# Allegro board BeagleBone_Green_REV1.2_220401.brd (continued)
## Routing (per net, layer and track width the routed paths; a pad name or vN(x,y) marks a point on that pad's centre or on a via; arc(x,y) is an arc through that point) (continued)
EHRPWM2B: length 23.7
  TOP w0.121: v1(44.92,34.81) U5.T10
  LYR3 w0.133: v1(44.92,34.81) 44.38,35.35 44.38,35.73 43.38,36.73 43.38,40.68 41.55,42.52 37.87,42.52 35.81,44.58 34.78,44.58 33.89,45.46 33.89,49.13 P8.13
EMMC_RSTN: length 4.8
  TOP w0.203: U13.K5 28.7,43.26 v1(28.7,43.69)
  BOTTOM w0.121: R111.2 26.7,46.46 R162.2 ; R162.2 27.51,46.53 ; R162.2 27.51,44.88 v1(28.7,43.69)
EMMC_VCCI: length 2.1
  TOP w0.076: U13.C2 32.05,44.9 32.05,45.05 32.05,45.06 32.05,45.26 32.05,45.27 32.05,45.53
  TOP w0.121: v1(32.38,45.83) 32.37,45.83 32.36,45.82 32.35,45.82 32.05,45.53
  BOTTOM w0.121: C125.1 v1(32.38,45.83)
ENZ_KALDO_1P8V: length 3.4
  TOP w0.121: U5.B4 v1(50.52,22.81)
  BOTTOM w0.121: v1(50.52,22.81) 51.12,22.21 R54.2
ETH_RESETN: length 6.3
  TOP w0.121: U14.19 v1(25.83,34.61)
  BOTTOM w0.121: U1.4 27.2,37.74 26.8,37.34 R35.2 25.91,35.06 25.83,34.99 v1(25.83,34.61)
  BOTTOM w0.127: C27.1 R35.2
ETH_RST_GPIO1_8: length 36.7
  TOP w0.121: U5.E18 38.18,25.61 37.97,25.4 36.04,25.4 34.04,23.39 34.04,19.66 33.29,18.91 32.47,18.91 31.24,20.14 31.24,21.08 30.73,21.59 v1(30.73,24.02)
  LYR4 w0.133: v1(30.61,40.13) 30.61,37.85 30.73,37.72 30.73,25.78 31.24,25.27 31.24,24.53 v1(30.73,24.02)
  BOTTOM w0.121: U1.1 30.62,39.04 30.7,38.96 R34.2 31.14,39.6 v1(30.61,40.13)
ETH_TXD4: length 4.4
  TOP w0.121: U14.18 26.33,34.21 26.73,34.61 v1(29.21,34.61)
  BOTTOM w0.121: R145.1 v1(29.21,34.61)
GPIO0_7: length 45.8
  TOP w0.121: v1(36.07,18.03) 36.32,18.29 R50.1
  BOTTOM w0.121: P9.42 68.9,6.03 67.45,6.03 60.42,13.06 42.97,13.06 41.27,14.76 41.27,17.91 40.64,18.54 R51.1 39.75,19.18 39.37,19.56 37.85,19.56 37.21,20.19 36.7,20.19 36.47,19.96 36.47,19.45 36.07,19.05 v1(36.07,18.03)
GPIO0_7SRC: length 9.2
  TOP w0.121: R50.2 36.07,17.27 35.61,17.73 35.61,19.99 37.08,21.46 37.08,22.48 38.62,24.01 U5.C18
GPIO0_26: length 27.2
  TOP w0.121: v1(44.12,34.81) U5.T11
  LYR3 w0.133: P8.14 33.66,51.44 33.66,43.52 34.91,42.27 41.47,42.27 43.1,40.63 43.1,36.5 44.12,35.48 v1(44.12,34.81)
GPIO0_27: length 18.3
  TOP w0.121: U5.U12 44.12,35.61 44.12,36.17 43.56,36.73 43.56,44.7 43.95,45.09 43.95,48.28 43.01,49.22 40.95,49.22 P8.17
GPIO1_12: length 27.6
  TOP w0.121: v1(43.32,34.81) U5.T12
  LYR3 w0.133: P8.12 31.43,51.75 31.43,45.07 34.74,41.76 41.31,41.76 42.49,40.57 42.49,36.25 43.32,35.42 v1(43.32,34.81)
GPIO1_13: length 26
  TOP w0.121: v1(43.32,34.01) U5.R12
  LYR3 w0.121: 43.72,35.45 43.72,34.41 v1(43.32,34.01)
  LYR3 w0.133: 43.72,35.45 42.8,36.37 42.8,40.6 41.38,42.02 34.81,42.02 31.71,45.13 31.71,49.49 P8.11
GPIO1_14: length 22
  TOP w0.121: U5.V13 42.92,36.22 42.82,36.32 42.82,43.1 41.67,44.25 41.67,47.59 41.12,48.13 37.8,48.13 36.2,49.73 36.2,51.44 P8.16
GPIO1_15: length 19.4
  TOP w0.121: P8.15 37.47,49.07 38.03,48.51 41.15,48.51 41.92,47.75 41.92,44.36 43.07,43.21 43.07,36.43 43.32,36.17 43.32,35.61 U5.U13
GPIO1_16: length 55.9
  LYR4 w0.133: P9.15 36.32,3.05 32.26,3.05 31.24,4.06 31.24,6.86 31.75,7.37 31.75,18.95 31.24,19.46 31.24,21.79 33.53,24.08 33.53,37.21 35.56,39.24 37.72,39.24 37.97,39.5 37.97,42.09 38.82,42.94 v1(42.42,42.94)
  BOTTOM w0.133: v1(42.42,42.94) R160.2 R161.2
GPIO1_17: length 53.4
  TOP w0.121: v1(41.4,38.58) 41.45,38.58 42.12,37.92 U5.V14
  LYR4 w0.133: v1(35.31,6.48) 35.31,8.81 36.47,9.98 36.47,18.49 35.66,19.3 35.66,22.96 35.81,23.11 35.81,25.68 36.3,26.16 36.3,26.97 37.7,28.37 37.7,33.56 40.69,36.55 40.69,37.91 41.36,38.58 v1(41.4,38.58)
  BOTTOM w0.121: v1(35.31,6.48) 36.2,5.59 45.59,5.59 46.35,4.83 46.35,3.17 P9.23
GPIO1_28: length 38.6
  TOP w0.121: v1(37.01,37.34) 37.01,37.34 37.57,36.78 37.57,36.33 37.76,36.14 37.76,36.1 38.65,35.21 U5.U18
  LYR4 w0.133: v1(37.01,37.34) 36.96,37.34 36.53,36.91 36.53,36.63 36.31,36.41 35.14,36.41 34.29,35.56 34.29,22.1 34.27,22.08 34.27,22 34.04,21.77 34.04,17.78 32.66,16.41 32.66,5.87 32.38,5.59 P9.12
GPIO1_29: length 18.7
  TOP w0.121: P8.26 49.22,52.7 48.82,52.31 48.82,49.15 49.7,48.27 49.7,46.03 49.7,46.03 49.7,45.7 49.7,45.7 49.7,45.22 49.07,44.59 49.07,39.21 48.52,38.66 U5.V6
GPIO2_1: length 20.1
  TOP w0.121: P8.18 38.84,51.54 38.84,49.63 39.52,48.95 41.1,48.95 42.16,47.88 42.16,44.46 43.31,43.31 43.31,36.53 43.72,36.12 U5.V12
GPIO3_18: length 5.9
  TOP w0.121: U5.B12 43.32,22.81 43.32,22.23 42.6,21.52 42.09,21.52 40.77,20.19 v1(40.01,20.19)
  BOTTOM w0.121: v1(40.01,20.19) R51.2
GPIO3_19: length 28.2
  TOP w0.121: v1(42.52,23.61) U5.C13
  LYR4 w0.133: v1(42.52,23.61) 41.85,22.94 41.85,21.67 42.38,21.15 42.38,17.36 42.93,16.81 42.93,14 45.19,11.73 45.19,10.39 46.48,9.09 46.48,7.21 48.77,4.93 48.77,3.81 49.53,3.05 51.56,3.05 P9.27
GPIO3_20: length 5.9
  TOP w0.121: U5.D13 v1(42.52,25.21)
  BOTTOM w0.121: R20.2 42.55,20.95 42.12,21.38 42.12,24.81 v1(42.52,25.21)
GPIO3_21: length 59.2
  TOP w0.121: v1(38.75,41.34) 38.68,41.4 38.35,41.4 37.97,41.78 ; U5.A14 42.12,22.21 40.74,20.83 39.75,20.83 v1(39.12,20.19) 38.99,20.07 38.99,16.64 40.39,15.24 40.39,11.23 41.25,10.36 41.25,6.88 41.78,6.35 44.2,6.35 44.93,5.61 48.23,5.61 48.9,4.95 48.9,3.17 P9.25
  LYR3 w0.133: v1(35.05,23.55) 34.54,23.04 34.54,21.84 35.43,20.95 37.97,20.95 38.73,20.19 v1(39.12,20.19)
  LYR4 w0.133: v1(35.05,23.55) 35.05,34.16 35.31,34.42 37.34,34.42 38.73,35.81 38.73,36.32 38.48,36.58 38.48,41.07 v1(38.75,41.34)
GRN_C: length 2
  BOTTOM w0.381: P5.10 4.88,32.59 5.21,32.26 R132.2
GRNA: length 30.1
  TOP w0.121: v1(24.4,27.73) 24.33,27.8
  TOP w0.254: 24.33,27.8 U14.3
  BOTTOM w0.254: v1(24.4,27.73) 24.09,28.04 23.73,28.04 22.99,27.3 20.95,27.3 17.78,24.13 15.11,24.13 12.19,27.05 10.79,27.05 7.62,30.23 7.62,31.88 6.73,32.77 6.73,33.53 5.08,35.18 4.34,35.18 P5.9
HDMI_INT: length 12.2
  TOP w0.121: U5.U16 40.12,35.61 40.12,36.76 v1(39.86,37.02)
  BOTTOM w0.121: R170.1 R169.1 37.72,39.24 36.7,39.24 36.32,38.86 36.32,38.1 36.58,37.85 36.58,36.58 36.96,36.2 37.34,36.2 37.71,35.82 39.88,35.82 40.01,35.94 40.01,36.88 v1(39.86,37.02)
HDMICLK_DISN: length 5.4
  TOP w0.121: v1(39.5,39.5) 39.5,39.62 39.75,39.87 39.77,39.87 40.34,40.45 Y4.1 ; U5.V17 39.72,36.23 39.5,36.45 39.5,36.45 v1(39.49,36.46)
  LYR3 w0.133: v1(39.49,36.46) 39.46,36.5 39.46,39.46 v1(39.5,39.5)
I2C0_SCL: length 27.9
  TOP w0.121: R3.2 26.04,20.45 v1(26.92,19.56) ; U2.28 26.72,14.24 v1(26.92,14.03) ; v1(40.12,23.61) U5.C16
  LYR4 w0.133: v1(26.92,19.56) 27.56,18.92 27.56,14.67 v1(26.92,14.03)
  BOTTOM w0.121: v1(40.12,23.61) 39.72,23.21 39.72,21.69 39.14,21.1 37.67,21.1 36.17,22.61 31.98,22.61 31.72,22.86 U7.1 30.1,22.86 28.98,21.74 28.98,20.34 28.19,19.56 v1(26.92,19.56)
I2C0_SDA: length 33.2
  TOP w0.121: U2.27 26.48,13.84 v1(26.92,13.4) ; v1(36.07,19.68) 36.07,20.1 37.33,21.36 37.33,21.41 37.34,21.41 37.34,22.23 38.72,23.61 39.32,23.61 U5.C17 ; R4.2 v1(26.99,20.57)
  LYR3 w0.133: v1(36.07,19.68) 34.8,19.68 33.27,21.21 27.62,21.21 v1(26.99,20.57)
  LYR4 w0.133: v1(26.92,13.4) 27.81,14.29 27.81,19.75 v1(26.99,20.57)
  BOTTOM w0.121: v1(26.99,20.57) 26.42,20 26.42,19.3 26.67,19.05 28.32,19.05 29.34,20.07 30.48,20.07 30.82,20.41 U7.3
I2C1_SCL: length 25.2
  TOP w0.121: U5.A16 v1(40.12,22.01)
  TOP w0.133: v1(40.01,6.99) 40.01,6.73 41.15,5.59 41.15,3.05 P9.17
  LYR4 w0.133: v1(40.01,6.99) 43.31,10.29 43.48,10.29 44.25,11.06 44.25,11.67 41.87,14.05 41.87,14.85 41.23,15.49 41.23,20.75 40.12,21.86 v1(40.12,22.01)
I2C1_SDA: length 23.1
  TOP w0.121: U5.B16 v1(40.12,22.81)
  LYR4 w0.133: v1(40.12,22.81) 39.71,22.4 39.71,21.83 41,20.55 41,15.4 41.64,14.76 41.64,13.95 44.02,11.57 44.02,11.16 43.4,10.54 42.99,10.54 39.6,7.15 39.6,4.85 P9.18
I2C2_SCL: length 74.8
  TOP w0.121: v1(36.7,23.37) 37.47,23.37 38.51,24.41 39.32,24.41 U5.D17 ; J4.1 74.19,21.54 v1(73.66,21.02)
  LYR3 w0.133: v1(39.73,13.59) 44.42,13.59 47.6,10.41 53.21,10.41 55.65,12.85 68.61,12.85 73.66,17.91 v1(73.66,21.02)
  LYR4 w0.133: P9.19 41.4,3.05 39.42,3.05 38.63,3.84 38.63,12.49 v1(39.73,13.59) 37.47,15.85 37.47,20.35 37.1,20.71 37.1,22.97 v1(36.7,23.37)
  BOTTOM w0.121: v1(73.66,21.02) 73.15,21.52 R177.2
I2C2_SDA: length 72.9
  TOP w0.121: J4.2 v1(74.3,19.54) ; v1(36.7,24) 36.83,23.88 37.47,23.88 38.4,24.81 U5.D18
  LYR3 w0.133: v1(39.88,12.83) 40.13,13.08 44.53,13.08 47.43,10.18 53.41,10.18 55.8,12.57 68.82,12.57 74.02,17.78 74.02,19.27 v1(74.3,19.54)
  LYR4 w0.133: P9.20 41.53,3.43 39.37,3.43 38.86,3.94 38.86,11.81 v1(39.88,12.83) 40.15,13.1 40.15,13.74 39.79,14.1 39.66,14.1 37.74,16.01 37.74,20.52 37.34,20.93 37.34,23.37 v1(36.7,24)
  BOTTOM w0.121: v1(74.3,19.54) 73.92,19.54 73.91,19.53 R178.2
JTAG_EMU0: length 23.6
  TOP w0.121: v1(41.72,23.61) U5.C14 ; R23.2 36.06,11.87 34.29,13.64 v1(34.29,14.92)
  LYR3 w0.133: v1(34.29,14.92) 34.86,15.49 38.35,15.49 38.61,15.75 v1(42.42,15.75)
  LYR4 w0.133: v1(41.72,23.61) 41.72,23.24 41.59,23.11 41.59,21.55 41.96,21.18 41.96,21.11 41.97,21.1 41.97,16.19 v1(42.42,15.75)
  BOTTOM w0.121: P2.13 v1(34.29,14.92)
JTAG_EMU1: length 15.3
  TOP w0.121: R24.2 36.26,15.11 v1(36.07,14.92) ; v1(39.73,15.24) 39.65,15.24 38.59,16.3 38.59,20.3 39.5,21.21 40.77,21.21 41.72,22.16 41.72,22.81 U5.B14
  BOTTOM w0.121: v1(36.07,14.92) P2.14 39.18,14.92 39.5,15.24 v1(39.73,15.24)
JTAG_TCK: length 24.1
  TOP w0.121: U5.A12 43.72,22.26 43.4,21.94 43.4,21.94 42.73,21.27 42.35,21.27 40.39,19.3 40.39,15.88 40.89,15.37 40.89,12.19 v1(41.15,11.94)
  LYR3 w0.133: v1(34.29,12.38) 40.7,12.38 v1(41.15,11.94)
  BOTTOM w0.121: P2.9 v1(34.29,12.38) 34.29,13.46 34.1,13.65 P2.11
JTAG_TDI: length 24.1
  TOP w0.121: U5.B11 44.12,22.81 44.12,22.17 42.87,20.92 42.51,20.92 40.8,19.21 40.8,16.06 41.27,15.59 41.27,12.42 v1(41.8,11.9)
  BOTTOM w0.121: v1(41.8,11.9) 41.42,11.52 40.5,11.52 39.46,10.48 36.26,10.48 34.35,8.57 P2.3
JTAG_TDO: length 23.7
  TOP w0.121: U5.A11 44.52,22.04 44.2,21.72 44.2,21.08 43.56,20.45 42.54,20.45 42.54,20.44 41.15,19.05 41.15,16.32 41.66,15.81 41.66,12.85 42.32,12.19 42.32,11.71 v1(41.83,11.23)
  LYR3 w0.133: v1(34.29,11.11) 35.04,11.86 40.18,11.86 40.82,11.23 v1(41.83,11.23)
  BOTTOM w0.121: P2.7 v1(34.29,11.11)
JTAG_TMS: length 29
  TOP w0.121: U5.C11 v1(44.12,23.61) ; v1(44.2,8.89) 44.64,9.33 44.64,14.26 45.09,14.71 v1(45.09,15.95)
  LYR4 w0.133: v1(44.12,23.61) 44.12,21.87 44.39,21.6 44.39,16.27 44.7,15.95 v1(45.09,15.95)
  BOTTOM w0.121: v1(44.2,8.89) 43.69,9.4 41.66,9.4 40.2,7.94 35.5,7.94 34.86,7.3 P2.1
JTAG_TRSTN: length 25.6
  TOP w0.121: R25.1 36.83,7.49 36.64,7.3 v1(36.07,7.3) ; v1(42.55,8.89) 42.57,8.92 42.57,12.42 41.91,13.08 41.91,16 41.4,16.51 41.4,18.92 42.67,20.19 43.69,20.19 44.45,20.95 44.45,21.59 44.92,22.06 44.92,22.81 U5.B10
  BOTTOM w0.121: v1(42.55,8.89) 41.66,8.89 40.26,7.49 39.12,7.49 38.93,7.3 P2.2 v1(36.07,7.3)
LCD_DATA0: length 34.3
  TOP w0.121: U5.R1 52.63,33.61 53.92,34.9 57.25,34.9 v1(57.89,35.53) ; R95.1 v1(75.95,48.26)
  LYR3 w0.133: v1(75.95,48.26) 75.44,47.75 74.17,47.75 72.77,46.35 72.77,45.34 72.14,44.7 71.37,44.7 68.45,41.78 65.91,41.78 65.02,40.89 62.1,40.89 60.96,39.75 60.96,38.61 v1(57.89,35.53)
  BOTTOM w0.121: P8.45 75.56,48.64 v1(75.95,48.26) R95.1
LCD_DATA1: length 36.5
  TOP w0.121: R94.1 v1(74.17,48.39) ; U5.R2 51.72,33.62 52.11,34.01 52.68,34.01 52.68,34.01 52.92,34.25 52.92,34.25 53.92,35.26 55.07,35.26 55.37,35.56 v1(57.15,35.56)
  LYR3 w0.133: v1(57.15,35.56) 60.58,38.99 60.58,40.01 61.85,41.27 64.9,41.27 65.66,42.04 68.2,42.04 71.25,45.09 71.95,45.09 72.36,45.5 72.36,46.58 v1(74.17,48.39)
  BOTTOM w0.121: P8.46 74.17,51.31 v1(74.17,48.39) R94.1
LCD_DATA2: length 37.8
  TOP w0.121: P8.43 73.03,48.64 v1(73.28,48.39) ; v1(73.28,48.39) 73.53,48.39 74.04,48.9 76.07,48.9 76.83,48.13 R75.1 ; v1(73.28,48.39) R93.1 ; v1(51.32,34.01) U5.R3
  LYR3 w0.133: v1(73.28,48.39) 71.2,46.3 71.2,45.67 67.82,42.29 65.41,42.29 64.77,41.66 61.59,41.66 60.2,40.26 60.2,39.24 55.96,35 52.44,35 51.59,34.16 51.58,34.16 51.44,34.01 v1(51.32,34.01)
  BOTTOM w0.121: R93.1 v1(73.28,48.39)
LCD_DATA3: length 36.3
  TOP w0.121: P8.44 71.93,51.61 71.93,49.16 72.39,48.7 v1(72.39,48.39) R92.1 ; v1(50.52,34.01) U5.R4
  LYR3 w0.133: v1(50.52,34.01) 50.93,34.42 51.49,34.42 52.35,35.28 55.6,35.28 59.82,39.5 59.82,40.51 61.34,42.04 64.64,42.04 65.15,42.55 67.56,42.55 70.74,45.72 70.74,46.74 v1(72.39,48.39)
  BOTTOM w0.121: R92.1 v1(72.39,48.39)
LCD_DATA4: length 28.8
  TOP w0.121: U5.T1 52.67,34.41 53.98,35.71 v1(54.76,35.71)
  LYR3 w0.133: v1(54.76,35.71) 55.52,35.71 59.44,39.62 59.44,40.77 61.09,42.42 64.52,42.42 64.9,42.8 67.11,42.8 v1(69.09,44.78)
  BOTTOM w0.121: P8.41 68.38,48.06 R66.2 68.33,47.5 67.89,47.07 67.89,45.52 68.33,45.09 R91.1 68.78,45.09 v1(69.09,44.78)
LCD_DATA5: length 31.6
  TOP w0.121: v1(54.76,36.42) 54.3,36.42 52.69,34.81 52.12,34.81 U5.T2
  LYR3 w0.133: v1(67.79,44.63) 67.75,44.63 67.07,43.94 65.53,43.94 64.39,42.8 60.83,42.8 59.05,41.02 59.05,39.75 55.73,36.42 v1(54.76,36.42)
  BOTTOM w0.121: P8.42 69.22,51.44 69.22,49.91 68.33,49.02 67.82,49.02 67.18,48.39 R65.2 67.64,47.04 67.64,45.54 R90.1 67.18,44.96 67.31,44.83 67.59,44.83 v1(67.79,44.63)
LCD_DATA6: length 28.3
  TOP w0.121: U5.T3 51.28,34.77 v1(51.28,34.82)
  LYR3 w0.133: v1(51.28,34.82) 52.2,35.74 53.5,35.74 54.72,36.96 55.75,36.96 58.71,39.92 58.71,42.07 60.38,43.74 64.19,43.74 64.69,44.25 65.83,44.25 66.26,44.68 66.26,45.47 v1(65.99,45.75)
  BOTTOM w0.121: P8.39 66.29,48.51 R64.2 65.79,46.99 65.79,45.95 v1(65.99,45.75) 66.29,45.44 R89.1
LCD_DATA7: length 31.1
  TOP w0.121: v1(50.52,34.81) U5.T4
  LYR3 w0.133: v1(65.66,44.65) 64.59,44.65 63.91,43.97 60.23,43.97 58.29,42.04 58.29,40.01 55.63,37.34 54.74,37.34 53.47,36.07 51.78,36.07 v1(50.52,34.81)
  BOTTOM w0.121: P8.40 66.55,51.31 66.55,49.78 65.02,48.26 R63.2 65.15,47.5 65.53,47.12 65.53,45.95 65.02,45.44 R88.1 65.23,45.09 v1(65.66,44.65)
LCD_DATA8: length 24.1
  TOP w0.121: v1(53.59,36.83) 53.34,36.58 53.34,35.84 52.71,35.21 U5.U1
  LYR3 w0.133: v1(53.59,36.83) 54.48,37.72 55.5,37.72 57.91,40.13 57.91,42.04 60.08,44.21 63.68,44.21 63.93,44.46 63.93,45.67 v1(63.86,45.75)
  BOTTOM w0.121: P8.37 64.14,48.9 R62.2 63.63,46.99 63.63,45.97 v1(63.86,45.75) 64.14,45.47 R87.1
LCD_DATA9: length 27.9
  TOP w0.121: v1(53.59,37.47) 53.09,36.96 53.09,35.97 52.73,35.61 52.36,35.61 51.96,35.21 U5.U2
  LYR3 w0.133: v1(63.53,44.63) 58.98,44.63 57.53,43.18 57.53,40.26 55.37,38.1 54.23,38.1 v1(53.59,37.47)
  BOTTOM w0.121: P8.38 64.26,51.56 64.26,49.5 62.87,48.11 R61.2 63.37,46.99 63.37,45.59 R86.1 63.32,44.63 v1(63.53,44.63)
LCD_DATA10: length 27.1
  TOP w0.121: U5.U3 51.32,35.61 51.88,35.61 52.12,35.85 52.12,37.41 v1(52.22,37.52)
  LYR3 w0.133: v1(52.22,37.52) 53.19,38.48 55.24,38.48 57.15,40.39 57.15,43.43 58.8,45.09 61.09,45.09 v1(61.75,45.75)
  BOTTOM w0.121: R85.1 61.98,45.52 v1(61.75,45.75) 61.47,46.02 61.47,46.99 R60.2 61.98,47.75 63.88,49.66 63.88,51.69 P8.36
LCD_DATA11: length 25
  TOP w0.121: v1(51.18,37.21) 50.52,36.55 50.52,35.61 U5.U4 ; v1(56.26,48.39) R84.1
  LYR3 w0.133: v1(51.18,37.21) 51.41,37.44 51.41,38.51 51.87,38.96 51.87,45.26 54.58,47.98 55.85,47.98 v1(56.26,48.39)
  BOTTOM w0.121: P8.34 60.07,52.7 58.67,51.31 57.28,51.31 56.77,50.8 56.77,48.9 v1(56.26,48.39) R84.1
LCD_DATA12: length 24.2
  TOP w0.121: U5.V2 51.72,37.72 v1(52.2,38.2)
  LYR3 w0.133: v1(52.2,38.2) 52.59,38.6 52.59,44.34 53.31,45.06 58.14,45.06 58.45,45.36 60.66,45.36 v1(61.09,45.8)
  BOTTOM w0.121: P8.35 60.71,48.01 R58.2 61.21,46.99 61.21,45.92 v1(61.09,45.8) 60.71,45.42 R83.1
LCD_DATA13: length 22.5
  TOP w0.121: v1(51.23,36.55) 50.92,36.24 U5.V3
  LYR3 w0.133: v1(59.39,45.77) 58.34,45.77 57.89,45.31 52.93,45.31 52.12,44.5 52.12,38.73 51.74,38.35 51.74,37.06 v1(51.23,36.55)
  BOTTOM w0.121: P8.33 59.82,49.66 R57.2 59.31,46.99 59.31,45.85 v1(59.39,45.77) 59.82,45.34 R82.1
LCD_DATA14: length 19.7
  TOP w0.121: P8.31 56.77,49.15 53.98,49.15 53.59,48.77 53.59,48.13 R56.2 52.64,47.62 52.43,47.41 52.43,45.05 52.96,44.51 R81.1 52.45,43.94 52.45,42.55 51.94,42.04 51.94,38.86 50.12,37.04 U5.V4
LCD_DATA15: length 24.4
  TOP w0.121: R80.1 53.98,48.26 v1(54.23,48.51) ; v1(49.72,34.81) U5.T5
  LYR3 w0.133: v1(49.72,34.81) 49.72,36.89 50.8,37.97 50.8,39.24 51.44,39.88 51.44,45.29 54.23,48.08 v1(54.23,48.51)
  BOTTOM w0.121: P8.32 57.66,52.7 56.52,51.56 56.52,49.66 56.01,49.15 54.86,49.15 v1(54.23,48.51) R55.2
LCD_DE: length 15.2
  TOP w0.121: R48.2 50.16,41.91 50.8,42.55 50.8,44.7 50.48,45.03 50.48,47.81 51.56,48.9 51.56,50.8 52.07,51.31 53.85,51.31 55.24,52.7
LCD_HSYNC: length 11.5
  TOP w0.121: 55.24,50.16 54.1,50.16 52.14,48.2 52.14,42.74 51.44,42.04 R47.2
LCD_PCLK: length 9.3
  TOP w0.121: P8.28 51.18,51.18 51.18,49.02 50.2,48.04 50.2,45.5 50.2,45.49 50.2,44.99 50.16,44.95 R45.2
LCD_VSYNC: length 6.6
  TOP w0.121: R46.2 51.44,45.72 51.05,46.1 51.05,47.56 52.7,49.22 P8.27
LCDDE: length 6.9
  TOP w0.121: R48.1 v1(50.16,39.12) ; v1(48.92,34.01) U5.R6
  LYR3 w0.121: v1(48.92,34.01) 49.32,34.41 49.32,37.26
  LYR3 w0.133: 49.32,37.26 49.53,37.47 49.53,38.48 v1(50.16,39.12)
LCDPCLK: length 7.8
  TOP w0.121: R45.1 50.16,42.8 49.66,42.29 49.66,37.55 49.32,37.21 U5.V5
LCDVHYNC: length 7.1
  TOP w0.121: v1(51.44,39.12) R47.1 ; v1(49.72,34.01) U5.R5
  LYR3 w0.121: v1(49.72,34.01) 50.12,34.41 50.12,35.13
  LYR3 w0.133: v1(51.44,39.12) 51.08,38.76 51.08,37.74 50.12,36.79 50.12,35.13
LCDVSYNC: length 9.1
  TOP w0.121: U5.U5 49.72,35.61 49.72,37.02 50.71,38.01 50.71,41.95 51.44,42.67 R46.1
LDO_PGOOD: length 35.6
  TOP w0.121: U2.46 21.46,18.99 v1(20.83,19.62) ; U5.B5 v1(49.72,22.81)
  LYR3 w0.133: v1(20.83,19.62) 21.53,20.32 25.91,20.32 27.05,21.46 33.53,21.46 34.9,20.09 37.29,20.09 38.18,19.2 46.35,19.2 47.35,20.19 49.4,20.19 49.72,20.51 v1(49.72,22.81)
LEDAA: length 6.1
  TOP w0.381: D2.2 6.38,49.02 7.77,47.62 R72.2
LEDAC: length 17.2
  TOP w0.121: D2.1 4.71,49.02 4.72,49.02 v1(4.84,49.02) ; Q1.6 19.29,45.35 19.05,45.59 v1(18.54,45.59)
  LYR3 w0.133: v1(18.54,45.59) 16.64,47.5 7.72,47.5 6.2,49.02 v1(4.84,49.02)
LEDBA: length 5.7
  TOP w0.381: R73.2 6.29,46.74 D3.2
LEDBC: length 20.3
  TOP w0.121: v1(6.43,48.11) 4.86,48.11 4.13,47.37 D3.1 ; Q1.3 20.59,43.58 20.83,43.81 v1(21.21,43.81)
  LYR3 w0.133: v1(6.43,48.11) 7.42,47.12 15.11,47.12 18.41,43.81 v1(21.21,43.81)
LEDCA: length 5.9
  TOP w0.381: R74.2 7.37,45.85 6.48,44.96 D4.2
LEDCC: length 14.7
  TOP w0.121: v1(15.62,45.59) 16,45.21 16.51,45.21 16.62,45.1 Q2.6 ; D4.1 4.78,44.96 5,45.19 5,46.02 v1(5.31,46.33)
  LYR3 w0.133: v1(5.31,46.33) 5.77,46.79 14.43,46.79 v1(15.62,45.59)
LEDDA: length 6.3
  TOP w0.381: R71.2 7.43,44.96 5.78,43.31 D5.2
LEDDC: length 18.2
  TOP w0.121: Q2.3 v1(17.92,42.51) ; v1(3.42,43.21) 4.04,43.21 4.06,43.18 D5.1
  LYR3 w0.133: v1(3.42,43.21) 5.32,45.11 15.9,45.11 17.92,43.09 v1(17.92,42.51)
MDIO_CLK: length 14.5
  TOP w0.121: U14.17 26.83,34.17 26.95,34.29 28.7,34.29 28.83,34.16 32,34.16 32.51,34.67 33.4,34.67 35.31,32.77 35.69,32.77 36.7,31.75 37.72,31.75 38.35,31.11 38.82,31.11 U5.M18
MDIO_DATA: length 15
  TOP w0.121: U14.16 28.04,32.87 28.32,33.15 28.83,33.15 29.34,33.66 R119.2 30.45,33.18 31.97,33.18 32.26,33.46 32.26,33.91 32.66,34.31 33.38,34.31 35.18,32.51 35.56,32.51 36.58,31.5 37.59,31.5 38.28,30.81 39.32,30.81 U5.M17
MII1_COL: length 24.2
  TOP w0.121: v1(40.12,27.61) U5.H16
  LYR3 w0.133: v1(31.75,26.04) 31.11,26.04 30.99,25.91 30.99,25.27 30.86,25.15 29.84,25.15 29.72,25.27 29.72,26.42 29.84,26.54 32.38,26.54 32.51,26.67 32.51,27.69 32.77,27.94 36.02,27.94 36.4,27.56 39.7,27.56 39.75,27.61 v1(40.12,27.61)
  BOTTOM w0.121: R138.1 31.43,32.26 31.84,32.26 32.15,31.95 32.15,30.84 32.51,30.48 32.51,26.8 v1(31.75,26.04)
MII1_CRS_DV: length 25.6
  TOP w0.121: v1(36.83,28.41) 39.32,28.41 U5.H17 ; R139.1 v1(31.75,32.7)
  BOTTOM w0.121: v1(36.83,28.41) 36.43,28.01 36.43,24.49 36.33,24.38 36.17,24.38 36.07,24.49 36.07,30.1 35.81,30.35 32.96,30.35 32.86,30.45 32.86,30.57 32.98,30.68 34.88,30.68 34.96,30.76 34.96,30.88 34.85,30.99 34.11,30.99 33.88,31.22 33.63,31.22 33.4,30.99 32.5,30.99 32.4,31.09 32.4,33.05 32.3,33.15 31.85,33.15 31.75,33.05 v1(31.75,32.7)
MII1_REFCLK: length 18.5
  TOP w0.121: R124.1 31.69,26.92 v1(31.75,26.99) 31.81,27.05 32,27.05 32.11,26.95 32.11,26.58 32.2,26.49 32.33,26.49 32.46,26.62 32.46,26.75 32.68,26.97 33.3,26.97 33.42,26.85 33.42,26.12 33.32,26.02 32.59,26.02 32.51,25.94 32.51,25.73 32.59,25.65 33.32,25.65 33.4,25.58 33.4,25.35 33.32,25.27 32.59,25.27 32.51,25.2 32.51,24.97 32.59,24.89 33.71,24.89 33.78,24.97 33.78,25.25 33.88,25.35 34.17,25.35 34.3,25.47 34.3,25.64 34.21,25.73 33.91,25.73 33.78,25.86 33.78,26.09 33.86,26.16 34.98,26.16 35.05,26.24 35.05,26.47 34.98,26.54 33.86,26.54 33.78,26.62 33.78,26.85 33.86,26.92 34.98,26.92 35.08,27.03 35.08,27.2 34.98,27.3 33.91,27.3 33.78,27.43 R28.2
  BOTTOM w0.121: R140.1 31.75,26.8 v1(31.75,26.99)
MII1_RXCLK: length 23.8
  TOP w0.121: U5.L18 38.3,30.41 37.47,31.24 36.45,31.24 35.43,32.26 35.05,32.26 33.78,33.53 33.53,33.53 33.42,33.42 33.42,33 33.29,32.87 32.26,32.87 32.15,32.77 32.15,32.63 32.28,32.51 32.66,32.51 32.77,32.4 32.77,30.58 32.87,30.48 32.98,30.48 33.08,30.58 33.08,31.78 33.19,31.88 33.36,31.88 33.46,31.78 33.46,29.34 33.34,29.21 32.64,29.21 32.51,29.34 32.51,30.04 32.19,30.35 31.85,30.35 31.75,30.45 v1(31.75,30.8)
  BOTTOM w0.121: R131.1 30.99,27.3 31.11,27.43 31.88,27.43 32.26,27.81 32.26,30.29 v1(31.75,30.8)
MII1_RXD0: length 24.2
  TOP w0.121: v1(31.75,31.75) 31.75,31.56 R128.1 ; U5.M16 40.12,31.61 v1(39.32,31.61)
  LYR3 w0.133: v1(31.75,31.75) 31.37,31.75 30.86,32.25 30.86,35.97 30.96,36.07 31.22,36.07 31.47,36.32 31.75,36.32 32.01,36.07 32.28,36.07 32.38,35.97 32.38,35.15 32.28,35.05 31.37,35.05 31.24,34.92 31.24,34.29 31.37,34.16 32.28,34.16 32.38,34.06 32.38,33.25 32.28,33.15 31.37,33.15 31.24,33.02 31.24,32.42 31.37,32.3 38.63,32.3 v1(39.32,31.61)
MII1_RXD1: length 24.6
  TOP w0.121: v1(31.75,29.84) 31.5,30.1 31.24,30.1 R127.1 ; U5.L15 v1(40.92,30.01)
  LYR3 w0.121: 39.75,29.61 40.52,29.61 v1(40.92,30.01)
  LYR3 w0.133: v1(31.75,29.84) 31.5,30.1 30.96,30.1 30.1,30.96 30.1,31.88 29.97,32 29.74,32 29.62,31.88 29.62,30.71 30.99,29.34 31.88,29.34 32.16,29.62 32.16,30.12 32.89,30.86 32.89,31.14 32.99,31.24 33.17,31.24 33.27,31.14 33.27,30.71 33.38,30.61 33.55,30.61 33.66,30.71 33.66,31.14 33.76,31.24 33.93,31.24 34.04,31.14 34.04,30.71 34.14,30.61 34.32,30.61 34.42,30.71 34.42,31.14 34.52,31.24 34.7,31.24 34.8,31.14 34.8,30.71 34.9,30.61 35.08,30.61 35.15,30.68 35.15,31.14 35.26,31.24 36.2,31.24 36.32,31.11 36.32,30.51 36.42,30.4 37.11,30.4 37.24,30.53 37.24,30.99 37.33,31.08 37.6,31.08 39.07,29.61 39.75,29.61
MII1_RXD2: length 24.2
  TOP w0.121: U5.L16 v1(40.92,30.81) ; R126.1 30.99,29.24 31.09,29.34 31.39,29.34 31.5,29.24 31.5,28.99 31.6,28.89 31.78,28.89 31.88,28.99 31.88,29.36 31.98,29.46 32.16,29.46 32.26,29.36 32.26,28.99 32.36,28.89 33.66,28.89 33.78,29.02 33.78,32.03 33.68,32.13 33.12,32.13 33.02,32.23 33.02,32.41 33.12,32.51 33.55,32.51 33.66,32.61 33.66,32.92 33.76,33.02 33.94,33.02 34.69,32.27 34.69,30.85 34.8,30.73 34.96,30.73 35.07,30.85 35.07,31.91 35.17,32.01 35.31,32.01 35.58,31.74 35.58,31.36 35.68,31.26 36.07,31.26 36.21,31.11 36.21,30.94 36.07,30.8 35.85,30.8 v1(35.84,30.81)
  BOTTOM w0.121: v1(40.92,30.81) 40.92,30.56 40.77,30.41 39.95,30.41 39.37,29.83 39.37,29.59 39.12,29.34 37.21,29.34 37.01,29.54 36.47,29.54 36.35,29.67 36.35,30.81 36.23,30.93 35.96,30.93 v1(35.84,30.81)
MII1_RXD3: length 24.2
  TOP w0.121: U5.L17 39.72,30.2 39.54,30.01 37.69,30.01 37.59,30.11 37.59,30.76 37.49,30.86 37.31,30.86 37.23,30.78 37.23,30.2 37.13,30.1 36.86,30.1 36.6,30.35 36.35,30.35 36.09,30.1 35.94,30.1 35.69,30.35 34.9,30.35 34.8,30.25 34.8,28.93 34.9,28.83 35.08,28.83 35.18,28.93 35.18,29.17 35.3,29.29 35.38,29.29 35.47,29.2 35.47,28.93 35.57,28.83 35.76,28.83 35.86,28.93 35.86,29.34 35.96,29.45 36.09,29.45 36.18,29.36 36.18,28.66 36.09,28.57 34.52,28.57 34.42,28.68 34.42,32.16 34.32,32.26 34.14,32.26 34.04,32.16 34.04,28.7 33.91,28.57 31.62,28.57 R125.1
MII1_RXDV: length 25.5
  TOP w0.121: U5.J17 v1(40.12,29.21) ; v1(22.73,35.05) 22.53,35.05 22.12,34.65 R129.1
  LYR3 w0.133: v1(40.12,29.21) 39.99,29.34 38.96,29.34 38.23,30.07 36.37,30.07 35.71,29.41 35.43,29.41 34.8,30.05 32.81,30.05 32.63,29.86 32.63,29.32 31.98,28.68 30.33,28.68 29.72,29.29 29.39,29.29 29.38,29.3 28.74,29.3 28.22,29.81 28.04,29.81 27.83,29.61 27.64,29.61 27.45,29.8 27.45,29.99 27.66,30.19 27.66,30.38 27.47,30.57 27.28,30.57 27.08,30.36 26.89,30.36 26.7,30.55 26.7,30.74 26.9,30.95 26.9,31.13 25.4,32.64 23.88,32.64 23.11,33.4 23.11,34.67 v1(22.73,35.05)
MII1_RXERR: length 24.2
  TOP w0.121: v1(33.03,29.64) 33.02,29.65 33.02,29.97 32.49,30.51 32.49,31.03 32.37,31.15 32.27,31.15 32.15,31.28 32.15,31.52 32.27,31.64 32.37,31.64 32.49,31.76 32.49,32.03 32.29,32.23 31.08,32.23 30.99,32.14 R133.1 ; U5.J15 v1(40.92,29.21)
  LYR3 w0.121: v1(40.92,29.21) 40.52,28.81 39.86,28.81
  LYR3 w0.133: 39.86,28.81 39.47,28.81 39.3,28.98 39.01,28.98 38.91,28.88 38.91,28.57 38.82,28.48 38.55,28.48 38.46,28.57 38.46,29.44 38.33,29.57 38.13,29.57 38.05,29.49 38.05,28.55 37.95,28.46 37.77,28.46 37.59,28.63 37.59,29.59 37.43,29.75 36.43,29.75 36.14,29.46 36.14,28.71 36,28.56 35.81,28.56 35.67,28.71 35.67,29.01 35.57,29.11 35.38,29.11 35.28,29.01 35.28,28.67 35.17,28.56 34.98,28.56 34.83,28.71 34.83,29.57 34.71,29.69 34.52,29.69 34.42,29.59 34.42,28.65 34.29,28.52 34.1,28.52 33.96,28.66 33.96,29.62 33.81,29.77 33.63,29.77 33.5,29.64 33.5,28.62 33.38,28.5 33.19,28.5 33.03,28.66 v1(33.03,29.64)
MII1_TXCLK: length 22.4
  TOP w0.121: U5.K18 37.47,29.61 37.26,29.82 35.74,29.82 35.64,29.92 v1(35.55,29.92)
  LYR3 w0.133: v1(35.55,29.92) 35.15,30.33 32.72,30.33 32.39,30 32.39,29.5 31.88,28.98 30.84,28.98 29.49,30.33 28.35,30.33 27.74,30.94 27.74,31.34 27.38,31.7 27.18,31.7 27.05,31.83 27.05,32.07 27.18,32.21 27.64,32.21 27.82,32.39 27.82,32.58 27.66,32.74 27.18,32.74 27.04,32.87 27.04,33.06 27.18,33.2 28.17,33.2 v1(28.57,33.6)
  BOTTOM w0.121: v1(28.57,33.6) 28.57,34.62 29.01,35.05 30.48,35.05 R134.1
MII1_TXD0: length 28.9
  TOP w0.121: U5.K17 39.32,29.21 37.36,29.21 37.09,29.48 36.65,29.48 36.43,29.27 36.43,28.56 36.2,28.32 32.86,28.32 32,27.46 28.93,27.46 v1(28.45,27.94) ; R158.1 v1(20.45,38.23)
  LYR4 w0.133: v1(28.45,27.94) 26.72,29.67 26.72,34.82 25.32,36.22 22.45,36.22 v1(20.45,38.23)
MII1_TXD1: length 28.1
  TOP w0.121: R166.1 v1(20.45,37.34) ; v1(40.12,30.01) U5.K16
  LYR3 w0.133: v1(40.12,30.01) 39.1,30.01 37.57,31.55 32.74,31.55 32.16,30.96 32.16,30.63 31.92,30.39 31.08,30.39 30.35,31.11 30.35,33.66 29.84,34.16 28.27,34.16 28.14,34.3 28.14,34.56 28,34.7 27.74,34.7 27.6,34.56 27.6,34.3 27.47,34.16 27.2,34.16 27.07,34.3 27.07,34.56 26.94,34.7 26.67,34.7 26.54,34.56 26.54,34.3 26.4,34.16 25.02,34.16 21.84,37.34 v1(20.45,37.34)
MII1_TXD2: length 28.8
  TOP w0.121: U5.K15 v1(41.72,30.01) ; R171.1 v1(20.45,36.45)
  LYR3 w0.121: 39.88,30.41 41.32,30.41 41.72,30.01 v1(41.72,30.01)
  LYR3 w0.133: v1(20.45,36.45) 20.04,36.86 20.04,37.61 20.25,37.82 21.82,37.82 24.63,35.01 29.38,35.01 30.61,33.78 30.61,32.16 31.42,31.34 32.2,31.34 32.64,31.78 37.71,31.78 39.08,30.41 39.88,30.41
MII1_TXD3: length 28.5
  TOP w0.121: v1(36.83,29.08) 36.83,29.06 37.08,28.81 U5.J18 ; R172.1 v1(20.45,35.56) ; v1(35.56,33.27) 33.78,35.05 31.42,35.05 31.29,34.92 31.29,34.62 31.21,34.53 30.79,34.53 30.73,34.59 30.73,35.2 30.63,35.31 30.35,35.31 30.25,35.2 30.25,34.67 30.12,34.54 29.84,34.54 29.72,34.66 29.72,35.74 29.39,36.07 27.94,36.07 27.43,35.56 v1(25.4,35.56)
  LYR4 w0.133: v1(36.83,29.08) 36.32,29.59 36.32,32.51 v1(35.56,33.27) ; v1(20.45,35.56) 21.72,34.29 23.74,34.29 23.88,34.42 23.88,35.56 24.15,35.83 25.13,35.83 v1(25.4,35.56)
MII1_TXEN: length 28.3
  TOP w0.121: R149.1 21.08,39.24 v1(21.59,39.75) ; v1(40.12,28.41) U5.J16
  LYR3 w0.133: v1(28.45,28.89) 28.99,28.35 33.01,28.35 33.14,28.22 36.32,28.22 36.55,27.99 39.7,27.99 v1(40.12,28.41)
  LYR4 w0.133: v1(21.59,39.75) 21.59,39.37 21.64,39.32 21.64,38.79 23.6,36.83 25.27,36.83 27.3,34.8 27.3,33.58 27.76,33.12 27.76,29.58 v1(28.45,28.89)
MMC0_CD: length 72.4
  TOP w0.121: v1(40.92,23.61) U5.C15
  LYR3 w0.133: v1(71.12,27.81) 71.12,19.68 66.73,15.29 55.22,15.29 54.28,16.23 54.28,18.06 53.21,19.13 51.56,19.13 51.16,19.53 47.12,19.53 46.43,18.85 35.33,18.85 v1(35.15,18.67)
  BOTTOM w0.121: v1(40.92,23.61) 40.52,23.21 40.52,21.84 39.53,20.85 36.09,20.85 35.42,20.18 35.42,19.31 35.15,19.05 v1(35.15,18.67) 34.67,18.67 34.61,18.73 P2.19 ; v1(71.12,27.81) 71.17,27.76 R157.1 72.77,28.7 73.03,28.96 79.25,28.96 79.59,29.3 P10.10
MMC0_CLKO: length 9.2
  TOP w0.121: R16.1 32.77,23.37 32.77,23.56 35.61,26.4 37.45,26.4 38.66,27.61 39.32,27.61 U5.G17
MMC0_CMD: length 84.4
  TOP w0.121: v1(32.38,20.32) 33.15,21.08 33.15,23.59 35.71,26.15 37.58,26.15 38.64,27.21 U5.G18
  LYR3 w0.133: v1(63.95,38.61) 63.25,37.91 63.25,35.94 64.26,34.92 67.95,34.92 69.22,33.66 70.23,33.66 72.16,31.72 72.16,18.95 67.56,14.35 55.12,14.35 54.56,13.79 48.41,13.79 44.19,18.01 39.18,18.01 38.55,17.39 38.55,17.39 38.45,17.29 34.08,17.29 31.98,19.39 31.98,19.91 v1(32.38,20.32)
  BOTTOM w0.121: R15.1 v1(63.95,38.61)
MMC0_DAT0: length 77.1
  TOP w0.121: v1(40.12,26.81) U5.G16
  LYR3 w0.133: v1(64.01,36.7) 64.29,36.98 68.94,36.98 73.25,32.66 73.25,18.01 68.45,13.21 55.5,13.21 54.56,12.27 48.25,12.27 45.99,14.53 44.97,14.53 42.59,16.92 40.11,16.92 v1(39.73,16.54)
  LYR4 w0.133: v1(40.12,26.81) 37.74,24.43 37.74,21.36 38.38,20.73 38.38,17.88 v1(39.73,16.54)
  BOTTOM w0.121: R21.1 v1(64.01,36.7)
MMC0_DAT1: length 75.2
  TOP w0.121: v1(40.92,26.81) U5.G15
  LYR3 w0.133: v1(39.73,17.12) 40,17.39 42.58,17.39 45.05,14.92 46.11,14.92 48.29,12.75 54.53,12.75 55.37,13.59 68.36,13.59 73,18.22 73,32.28 69.22,36.07 65.09,36.07 v1(64.42,35.4)
  LYR4 w0.133: v1(39.73,17.12) 38.68,18.16 38.68,20.8 38,21.49 38,24.28 39.98,26.26 40.37,26.26 v1(40.92,26.81)
  BOTTOM w0.121: R31.1 64.01,34.99 v1(64.42,35.4)
MMC0_DAT2: length 84.2
  TOP w0.121: v1(33.02,19.56) 33.15,19.56 33.42,19.83 33.42,23.48 35.84,25.9 36.11,25.9 36.12,25.9 37.71,25.9 38.22,26.41 U5.F18
  LYR3 w0.133: v1(63.08,40.42) 62.36,39.7 62.36,35.81 65.41,32.77 69.72,32.77 71.53,30.96 71.53,19.66 66.85,14.99 55.04,14.99 53.9,16.13 53.9,18.03 53.11,18.82 51.1,18.82 50.9,19.02 47.57,19.02 46.51,17.96 45.62,17.96 45.03,18.54 35.81,18.54 35.28,18.01 34.57,18.01 v1(33.02,19.56)
  BOTTOM w0.121: v1(63.08,40.42) 63.89,41.22 R2.1
MMC0_DAT3: length 84.5
  TOP w0.121: v1(32.38,19.56) 32.78,19.16 33.19,19.16 33.42,19.39 33.42,19.42 33.78,19.78 33.78,23.49 35.94,25.65 36.22,25.65 36.22,25.65 37.83,25.65 38.19,26.01 39.32,26.01 U5.F17
  LYR3 w0.133: v1(32.38,19.56) 34.32,17.63 38.46,17.63 39.08,18.25 44.67,18.25 48.23,14.68 67.01,14.68 71.86,19.53 71.86,31.27 69.98,33.15 68.96,33.15 68.2,33.91 64.77,33.91 62.74,35.94 62.74,39.37 v1(63.12,39.75)
  BOTTOM w0.121: v1(63.12,39.75) 63.7,40.34 R13.1
MMC1_CLK: length 52.8
  TOP w0.121: P8.21 45.64,49.61 45.64,49.07 45.76,48.95 48.06,48.95 48.18,48.83 48.18,48.58 48.06,48.46 45.76,48.46 45.64,48.34 45.64,48.1 45.76,47.98 48.06,47.98 48.18,47.86 48.18,47.62 48.06,47.5 45.76,47.5 45.64,47.38 45.64,47.14 45.76,47.02 48.06,47.02 48.18,46.89 48.18,46.65 48.06,46.53 45.99,46.53 45.87,46.41 R110.2 45.87,42.72 C6.1 R32.2 46.86,42.72
  TOP w0.203: U13.M6 27.94,42.52 v1(28.12,42.52)
  LYR4 w0.133: P8.21 44.41,49.49 44.41,49.16 44.54,49.03 45.18,49.03 45.31,48.9 45.31,48.63 45.18,48.49 44.54,48.49 44.41,48.36 44.41,48.09 44.54,47.96 45.18,47.96 45.31,47.83 45.31,47.56 45.18,47.43 44.54,47.43 44.41,47.29 44.41,47.03 44.52,46.91 45.06,46.91 45.21,46.76 45.21,45.44 44.88,45.11 42.14,45.11 41.55,45.69 37.69,45.69 36.65,44.65 36.65,42.88 34.92,41.15 29.49,41.15 v1(28.12,42.52)
MMC1_CMD: length 45.1
  TOP w0.203: U13.M5 27.8,43.15 28.18,43.15 v1(28.25,43.09)
  LYR4 w0.133: v1(43.51,45.62) 43.1,46.02 37.44,46.02 36.22,44.81 36.22,43.03 34.77,41.58 29.76,41.58 v1(28.25,43.09)
  BOTTOM w0.121: R33.2 R109.2 44.3,48.87 43.79,49.38 43.79,51.46 P8.20 41.48,51.64 41.48,49.14 41.36,49.02 39.92,49.02 39.8,48.9 39.8,48.66 39.92,48.54 41.36,48.54 41.48,48.42 41.48,48.18 41.36,48.06 39.92,48.06 39.8,47.93 39.8,47.69 39.92,47.57 41.36,47.57 41.48,47.45 41.48,47.21 41.36,47.09 39.92,47.09 39.8,46.97 39.8,46.73 39.92,46.61 41.36,46.61 41.48,46.49 41.48,45.8 41.92,45.35 43.24,45.35 v1(43.51,45.62)
MMC1_DAT0: length 42.7
  TOP w0.121: v1(37.49,44.73) 37.49,45.57 37.06,46 35.99,46 35.44,45.45 34.75,45.45 33.49,44.19 33.44,44.19 33.42,44.16 U13.A3
  LYR4 w0.133: P8.25 50.11,50.22 49.15,50.22 48.84,49.91 48.84,49.21 48.98,49.08 51.05,49.08 51.18,48.94 51.18,48.68 51.05,48.54 48.98,48.54 48.84,48.41 48.84,48.14 48.98,48.01 51.05,48.01 51.18,47.88 51.18,47.61 51.05,47.48 48.98,47.48 48.84,47.34 48.84,47.08 48.98,46.94 51.05,46.94 51.18,46.81 51.18,46.54 51.05,46.41 49.03,46.41 48.82,46.2 48.82,44.86 48.39,44.42 47.72,44.42 47.58,44.56 47.58,44.93 47.45,45.06 47.18,45.06 47.05,44.93 47.05,44.56 46.92,44.42 46.65,44.42 46.52,44.56 46.52,44.93 46.38,45.06 46.12,45.06 45.98,44.93 45.98,44.56 45.85,44.42 41.88,44.42 41.48,44.83 38.23,44.83 38.13,44.73 v1(37.49,44.73)
  BOTTOM w0.121: P8.25 50.16,47.52 R101.2 51.02,47.52 R37.2
MMC1_DAT1: length 44.3
  TOP w0.121: v1(37.97,45.16) 37.97,44.53 37.72,44.27 36.88,44.27 36.76,44.15 36.76,43.78 36.64,43.66 36.4,43.66 36.28,43.78 36.28,44.61 36.16,44.73 35.92,44.73 35.8,44.61 35.8,43.78 35.68,43.66 35.44,43.66 35.32,43.78 35.32,44.61 35.19,44.73 34.74,44.73 33.67,43.66 U13.A4
  LYR4 w0.133: v1(37.97,45.16) 41.61,45.16 41.99,44.78 45.24,44.78 45.77,45.31 45.77,46 46.08,46.31 48.05,46.31 48.18,46.44 48.18,46.71 48.05,46.84 45.95,46.84 45.82,46.98 45.82,47.24 45.95,47.38 48.05,47.38 48.18,47.51 48.18,47.78 48.05,47.91 45.95,47.91 45.82,48.04 45.82,48.31 45.95,48.44 48.05,48.44 48.18,48.58 48.18,48.84 48.05,48.98 46.64,48.98 46.51,49.11 v1(46.51,50.7)
  BOTTOM w0.121: R38.2 R102.2 49.3,48.03 48.9,48.43 48.9,51.44 P8.24 46.51,51.59 v1(46.51,50.7)
MMC1_DAT2: length 27.1
  TOP w0.076: 33.66,43.16 U13.A5
  TOP w0.121: v1(34.79,43.65) 34.3,43.16 33.66,43.16
  LYR3 w0.133: v1(27.11,45.82) 26.15,45.82 24.5,47.48 23.58,47.48 23.44,47.61 23.44,47.88 23.58,48.01 24.63,48.01 24.77,48.14 24.77,48.41 24.63,48.54 23.58,48.54 23.44,48.68 23.44,48.94 23.58,49.08 24.63,49.08 24.77,49.21 P8.5
  LYR4 w0.133: v1(27.11,45.82) 28.22,44.71 31.36,44.71 32.89,43.18 34.33,43.18 34.79,43.64 v1(34.79,43.65)
  BOTTOM w0.121: R39.2 R103.2 28.35,48.23 27.99,48.59 26.34,48.59 P8.5
MMC1_DAT3: length 28.2
  TOP w0.076: U13.B2 33.04,44.91 33.04,45.72
  TOP w0.121: 33.04,45.72 33.04,45.92 32.72,46.25 24.23,46.25 23.6,46.89 23.6,51.54 P8.6
  BOTTOM w0.121: R40.2 30.03,47.47 R104.2 30.86,48.39 30.34,48.91 26.71,48.91 26.04,49.58 26.04,51.44 P8.6
MMC1_DAT4: length 43
  TOP w0.076: U13.B3 33.05,44.41 33.4,44.41 33.6,44.62 33.6,44.91
  TOP w0.121: v1(39.24,51.21) 39.62,51.21 39.75,51.34 46.45,51.34 P8.23 ; 33.6,44.91 33.6,45.8 34.12,46.32 v1(34.85,46.32)
  LYR4 w0.133: v1(34.85,46.32) 35.4,46.32 35.53,46.45 35.53,47.21 35.67,47.35 36.09,47.35 36.22,47.21 36.22,46.46 36.35,46.33 36.75,46.33 36.88,46.46 36.88,47.3 37.01,47.44 40.74,47.44 40.87,47.57 40.87,47.84 40.74,47.97 37.24,47.97 37.11,48.1 37.11,48.37 37.24,48.5 40.74,48.5 40.87,48.64 40.87,48.9 40.74,49.04 36.89,49.04 36.3,49.63 36.3,50.77 36.91,51.38 38.68,51.38 38.86,51.21 v1(39.24,51.21)
  BOTTOM w0.121: R41.2 47.62,47.52 R105.2 46.79,49.33 P8.23
MMC1_DAT5: length 39.7
  TOP w0.076: 33.43,43.91 33.43,43.91 33.2,43.91 33.18,43.9 33.03,43.9 U13.B4
  TOP w0.121: 33.43,43.91 33.55,43.91 33.58,43.94 33.6,43.94 34.74,45.09 35.86,45.09 v1(36.32,45.54)
  LYR4 w0.133: v1(36.32,45.54) 37.74,46.96 38.15,46.96 38.29,46.83 38.29,46.39 38.42,46.26 38.69,46.26 38.82,46.39 38.82,46.83 38.95,46.96 39.22,46.96 39.35,46.83 39.35,46.39 39.49,46.26 39.75,46.26 39.89,46.39 39.89,46.83 40.02,46.96 40.29,46.96 40.42,46.83 40.42,46.39 40.55,46.26 40.82,46.26 40.95,46.39 40.95,46.83 41.09,46.96 41.36,46.96 41.49,46.83 41.49,46.39 41.62,46.26 41.89,46.26 42.02,46.39 42.02,46.83 42.16,46.96 42.42,46.96 42.56,46.83 42.56,46.39 42.69,46.26 42.96,46.26 43.09,46.39 43.09,46.83 43.22,46.96 43.71,46.96 43.84,47.1 43.84,47.34 43.71,47.48 41.54,47.48 41.4,47.61 41.4,47.88 41.54,48.01 43.71,48.01 43.84,48.14 43.84,48.41 43.71,48.54 41.54,48.54 41.4,48.68 41.4,48.94 41.54,49.08 43.31,49.08 44.04,49.81 44.04,50.71 45.09,51.75 P8.22
  BOTTOM w0.121: R42.2 R106.2 45.14,48.39 46.05,49.3 46.05,51.74 P8.22
MMC1_DAT6: length 24.9
  TOP w0.076: U13.B5 33.05,43.41 33.48,43.41
  TOP w0.121: 33.48,43.41 33.66,43.41 33.78,43.41 33.98,43.6 34.15,43.6 v1(34.16,43.59)
  LYR4 w0.133: 34.16,43.59 v1(34.16,43.59) 34.16,45.59 32.99,46.76 27.14,46.76 26.47,46.09 26.47,46.09 25.75,45.36 25.74,45.36 23.01,45.36 22.23,46.15 P8.3
  BOTTOM w0.121: R43.2 R107.2 23.34,49.05 P8.3
MMC1_DAT7: length 31.1
  TOP w0.076: 33.42,42.9 33.41,42.91 33.05,42.91 U13.B6
  TOP w0.121: v1(34.87,42.9) 33.42,42.9
  LYR4 w0.133: v1(34.87,42.9) 32.82,42.9 31.24,44.48 28.07,44.48 27.41,45.13 22.82,45.13 21.11,46.84 21.11,51.59 P8.4
  BOTTOM w0.121: R44.2 25.83,47.48 25.02,47.48 R108.2 25.02,47.54 23.59,48.96 23.59,51.34 P8.4
MODE2: length 3.9
  TOP w0.121: U14.15 28.11,32.37 v1(28.45,32.7)
  BOTTOM w0.121: v1(28.45,32.7) 28.66,32.7 28.81,32.85 28.81,32.87 29.04,33.1 29.06,33.1 29.62,33.66 R113.1 R138.2
OSC0_IN: length 8.2
  TOP w0.121: U5.V10 45.16,36.17 45.16,38.05 45.62,38.51 45.62,38.81 v1(45.49,38.94)
  BOTTOM w0.121: v1(45.49,38.94) 46.59,38.94 47.02,39.36 R17.1 47.02,40.3 47.09,40.38 C25.1 47.09,41.46 47.84,42.2 Y2.1
OSC0_OUT: length 6.6
  TOP w0.121: v1(44.92,39.27) 44.92,35.61 U5.U11
  BOTTOM w0.121: v1(44.92,39.27) 45.45,39.8 R17.2 46,40.64 R179.1
OSC1_IN: length 7.9
  TOP w0.121: C21.2 49.14,17.32 49.61,17.8 49.61,18.58 49.4,18.79 49.4,20.32 49.66,20.57 49.66,21.27 U5.A6 ; C21.2 49.16,16.85 ; C21.2 49.14,15.44 Y1.2
OSC1_OUT: length 8.5
  TOP w0.121: U5.A4 50.12,22.05 50.35,21.82 50.35,20.38 50.16,20.19 50.16,19.3 51.16,18.31 51.74,18.31 52.36,17.69 C22.2 52.36,15.54 Y1.1
P_BYPASS: length 3.1
  TOP w0.203: U2.47 21.06,18.94 20.82,19.18 20.65,19.18 20.42,19.41 v1(20.19,19.41)
  BOTTOM w0.381: C4.2 v1(20.19,19.41)
P_INT_LDO: length 2.8
  TOP w0.121: C3.2 20.38,20.32 19.79,19.73 19.79,19.24 20.03,19.01 20.27,19.01 20.66,18.61 U2.48
P_L1: length 1
  TOP w0.203: U2.20 23.46,11.18
  vias: v1(22.35,9.91) v1(22.99,9.91)
P_L2: length 0.6
  TOP w0.203: 24.66,11.53 U2.23
  vias: v1(24.64,9.91) v1(25.27,9.91)
P_L3: length 2.9
  BOTTOM w0.381: v1(29.21,17.4) 29.21,16.7 L3.1 28.57,16.7 v1(28.57,17.4) v1(29.21,17.4)
PHY_VDDCR: length 4
  TOP w0.254: v1(26.23,27.69) 26.21,27.69 25.83,28.06 U14.6
  BOTTOM w0.381: v1(26.23,27.69) 26.86,27.69 27.18,28 C134.1 C136.1
PHY_XTAL1: length 4.4
  TOP w0.121: v1(27.46,25.7) 27.46,26.52 27.33,26.64 Y3.3
  BOTTOM w0.121: R141.2 R142.1 C143.1 27.35,25.22 27.46,25.33 v1(27.46,25.7)
PHY_XTAL2: length 3.4
  TOP w0.121: U14.4 24.83,27.69 v1(24.97,27.56)
  BOTTOM w0.121: R143.2 R141.1 24.82,27.03 24.97,27.18 v1(24.97,27.56)
PHYX: length 3.3
  TOP w0.121: Y3.1 23.26,24.79 v1(23.04,24.57)
  BOTTOM w0.121: R143.1 C142.1 v1(23.04,24.57)
PMIC_INT: length 23.8
  TOP w0.121: U2.45 21.86,19.35 v1(21.59,19.62) 21.65,19.62 22.35,20.32 R1.2 ; U5.B18 37.59,21.88 37.59,21.03 36.96,20.4 v1(36.96,19.68)
  LYR3 w0.133: v1(21.59,19.62) 22.03,20.07 29.72,20.07 30.48,20.83 33.15,20.83 34.8,19.18 36.45,19.18 v1(36.96,19.68)
PMIC_PGOOD: length 32.9
  TOP w0.121: U2.26 26.35,13.44 26.56,13.23 26.56,13.13 v1(26.92,12.76) ; U16.2 31.75,10.19 31.32,10.62 30.35,10.62 v1(30.32,10.58) ; v1(40.92,22.81) U5.B15
  LYR3 w0.121: v1(40.92,22.81) 40.52,23.21 39.95,23.21
  LYR3 w0.133: v1(26.92,12.76) 27.5,12.76 29.7,10.57 30.28,10.57 30.3,10.58 v1(30.32,10.58) ; 39.95,23.21 37.69,23.21 37.34,22.86 36.07,22.86 35.81,23.11 35.81,23.75 35.56,24 34.8,24 34.04,23.24 v1(29.34,23.24)
  LYR4 w0.133: v1(29.34,23.24) 28.07,21.97 28.07,13.91 v1(26.92,12.76)
PMIC_POWR_EN: length 65.4
  TOP w0.121: v1(18.29,14.2) 18.69,14.2 18.73,14.24 U2.9 ; v1(48.92,23.61) U5.C6
  LYR3 w0.133: v1(18.29,14.2) 20.07,12.42 20.07,11.56 22.61,9.02 29.11,9.02 29.67,8.45 34.18,8.45 34.71,8.98 41.47,8.98 41.83,9.35 45.69,9.35 46.38,8.66 55.98,8.66 55.98,8.66 56.44,8.66 v1(58.52,10.74)
  LYR4 w0.133: v1(48.92,23.61) 48.92,22.45 50.42,20.95 53.21,20.95 54.74,19.43 54.99,19.43 57.91,16.51 57.91,11.3 58.47,10.74 v1(58.52,10.74)
PROC_A15: length 14
  TOP w0.121: v1(39.73,14.61) 39.55,14.61 38.34,15.81 38.34,20.47 39.34,21.46 40.37,21.46 40.92,22.01 U5.A15
  BOTTOM w0.121: R18.1 41.08,12.57 41.2,12.69 41.2,14 40.59,14.61 v1(39.73,14.61)
PWR_BUT: length 56.3
  TOP w0.121: U2.25 25.93,12.55 26.42,12.06 v1(26.92,12.06) ; v1(21.29,33.78) 19.46,33.78 13.51,39.73 S3.4 S3.2
  LYR4 w0.133: P9.9 28.88,2.87 28.88,10.11 v1(26.92,12.06) 26.16,12.83 26.16,21.46 23.83,23.8 22.33,23.8 20.32,25.81 20.32,32.82 v1(21.29,33.78)
PWR_LEDR: length 2.2
  TOP w0.381: D1.1 2.86,19.88 2.54,19.56 v1(2.54,19.48)
  BOTTOM w0.381: R12.2 v1(2.54,19.48)
RBIAS: length 2.7
  TOP w0.121: v1(21.27,28.26) 21.91,28.89 21.91,29.21 22.06,29.36 U14.32
  BOTTOM w0.121: v1(21.27,28.26) R144.1
RCLKIN: length 7.8
  TOP w0.121: v1(25.53,27.66) 25.52,27.66 25.33,27.85 U14.5
  BOTTOM w0.121: R142.2 25.76,27.05 ; 25.76,27.05 25.76,27.43 v1(25.53,27.66) ; 25.76,27.05 26.92,27.05 27.43,27.56 27.76,27.56 28.02,27.3 28.02,27 28.98,26.04 R140.2
REFCLKO: length 6.3
  TOP w0.121: U14.7 26.33,28.25 26.64,27.94 27.81,27.94 28.77,26.99 v1(29.21,26.99) 29.27,26.92 R124.2 R118.1
  BOTTOM w0.121: R131.2 v1(29.21,26.99)
RXD0/MODE0: length 4.1
  TOP w0.121: R128.2 29.97,30.48 29.84,30.35 29.34,30.35 29.21,30.48 v1(29.21,30.8) 29.02,30.8 28.59,30.36 U14.11
  BOTTOM w0.121: R128.2 v1(29.21,30.8)
RXD1/MODE1: length 4
  TOP w0.121: R127.2 29.97,29.46 29.88,29.37 29.34,29.37 29.21,29.5 v1(29.21,29.84) 29.19,29.86 28.89,29.86 U14.10
  BOTTOM w0.121: R127.2 v1(29.21,29.84)
RXD2/RMIISEL: length 4.1
  TOP w0.121: R126.2 29.97,28.57 29.84,28.45 29.34,28.45 29.21,28.57 v1(29.21,28.89) 28.74,29.36 U14.9
  BOTTOM w0.121: R126.2 v1(29.21,28.89)
RXD3/PHYAD2: length 4.3
  TOP w0.121: U14.8 26.83,28.47 26.96,28.34 28.81,28.34 v1(29.21,27.94) R125.2
  BOTTOM w0.121: R125.2 v1(29.21,27.94)
RXDV: length 3
  TOP w0.121: R129.2 21.72,33.99 21.72,32.92 22.28,32.37 U14.26
RXER/PHYAD0: length 4.1
  TOP w0.121: R133.2 29.97,31.37 29.88,31.27 29.34,31.27 29.21,31.4 v1(29.21,31.75) 28.83,31.37 U14.13
  BOTTOM w0.121: R133.2 v1(29.21,31.75)
RXN: length 18.4
  TOP w0.095: P5.2 17.14,33.92 16.89,34.17 16.26,34.17 16,33.92 16,32.64 16.64,32 17.64,32 18.43,32.79 19.29,32.79 20.09,31.99 20.09,30.39 20.66,29.83 20.94,29.83 v1(21.27,30.16) 21.34,30.23 21.9,30.23 22.03,30.36 U14.30
  BOTTOM w0.095: R121.1 v1(21.27,30.16)
  BOTTOM w0.121: C138.1 P5.2
RXP: length 15.9
  TOP w0.095: U14.31 22.02,29.86 21.93,29.95 21.68,29.95 21.53,29.79 21.53,29.46 v1(21.27,29.21) 20.94,29.55 20.54,29.55 19.81,30.28 19.81,31.88 19.18,32.51 18.54,32.51 17.75,31.72 16.52,31.72 15.72,32.52 15.72,34.04 15.47,34.29 P5.1
  BOTTOM w0.095: R120.1 v1(21.27,29.21)
  BOTTOM w0.121: C137.1 P5.1
SD_CLK: length 73.2
  TOP w0.121: v1(31.7,20.29) 31.7,20.37 31.62,20.45 C5.1 R16.2
  LYR3 w0.133: v1(68.83,35.18) 69.34,35.18 72.62,31.9 72.62,18.64 67.94,13.97 55.24,13.97 54.53,13.26 48.26,13.26 46.25,15.27 45.2,15.27 42.76,17.7 39.4,17.7 38.48,16.79 33.91,16.79 31.43,19.27 31.43,20.02 v1(31.7,20.29)
  BOTTOM w0.121: v1(68.83,35.18) 68.33,35.18 R152.2 68.2,35.81 69.52,35.81 69.67,35.66 P10.5 70.7,35.66
SD_CMD: length 6.9
  BOTTOM w0.121: 70.7,37.86 P10.3 69.96,37.86 68.76,39.06 68.37,39.06 67.98,39.45 R151.2 67.92,39.65 67.68,39.89 65.91,39.89 65.47,39.45 R15.2
SD_DAT0: length 7.1
  BOTTOM w0.121: 70.7,33.46 P10.7 69.41,33.46 68.45,34.42 R153.2 67.94,34.86 67.75,35.05 65.91,35.05 65.47,35.49 65.47,35.68 65.09,36.07 R21.2
SD_DAT1: length 6.7
  BOTTOM w0.121: 70.7,32.36 P10.8 69.49,32.36 68.58,33.27 R154.2 67.44,33.78 66.1,33.78 65.09,34.8 R31.2
SD_DAT2: length 6.9
  BOTTOM w0.121: R2.2 65.03,41.22 65.59,41.78 67.8,41.78 67.92,41.67 R150.2 68.51,41.22 69.67,40.06 P10.1 70.7,40.06
SD_DAT3: length 6.8
  BOTTOM w0.121: 70.7,38.96 P10.2 69.96,38.96 68.58,40.34 R155.2 67.92,40.54 67.68,40.78 65.91,40.78 65.47,40.34 R13.2
SPI1_CS0: length 24.7
  TOP w0.121: v1(43.32,23.61) U5.C12
  LYR4 w0.133: P9.28 50.7,6.45 49.68,6.45 49.17,6.96 49.17,8.74 46.99,10.92 46.99,13.69 45.94,14.74 45.03,14.74 43.92,15.85 43.92,21.26 43.32,21.86 v1(43.32,23.61)
SPI1_D0: length 29.4
  TOP w0.121: U5.B13 v1(42.52,22.81)
  LYR4 w0.133: v1(42.52,22.81) 42.11,22.4 42.11,21.79 42.66,21.25 42.66,17.64 43.21,17.09 43.21,15.66 44.65,14.21 44.65,13.13 45.49,12.29 45.49,11.38 48.65,8.22 48.65,5.52 49.02,5.16 49.02,4.24 49.96,3.3 51.82,3.3 52.07,3.05 54.1,3.05 55.24,1.91
SPI1_D1: length 27.1
  TOP w0.121: v1(43.32,24.41) U5.D12
  LYR4 w0.121: 43.72,23.11 43.72,24.01 v1(43.32,24.41)
  LYR4 w0.133: 55.24,4.45 54.53,4.45 51.44,7.54 51.44,8.03 50.68,8.79 49.5,8.79 47.29,11 47.29,13.74 45.97,15.06 45.04,15.06 44.15,15.95 44.15,21.46 43.72,21.89 43.72,23.11
SPI1_SCLK: length 30
  TOP w0.121: U5.A13 v1(42.52,22.01)
  LYR4 w0.133: P9.31 56.39,3.3 52.5,3.3 51.69,4.11 51.69,4.27 50.53,5.44 49.87,5.44 48.92,6.39 48.92,8.53 45.95,11.51 45.95,12.42 45.47,12.9 45.47,14.35 45.31,14.5 44.78,14.5 43.46,15.82 43.46,17.3 42.95,17.81 42.95,21.58 v1(42.52,22.01)
SYS_5V: length 66.7
  TOP w0.203: v1(19,14.76) 19.02,14.78 ; 19.02,14.78 19.28,15.04 U2.7 ; 19.02,14.78 19.17,14.64 U2.8 ; v1(22.99,19.11) 23.06,19 U2.42 ; U2.2 19.15,17.04 v1(18.8,17.4) ; U2.21 23.86,11.65 v1(24.05,11.46) 24.26,11.66 U2.22 ; U2.39 v1(24.26,19.11) ; U2.32 26.51,15.84 26.67,16 v1(26.68,16)
  TOP w0.381: v1(14.73,44.7) 14.35,45.09 12.45,45.09 12.32,44.96 12.32,47.62 ; v1(24.05,11.46) 24.05,10.9 v1(24.05,10.9) ; v1(18.08,14.77) 18.09,14.76 v1(18.52,14.76) v1(19,14.76)
  LYR4 w0.381: v1(14.73,44.7) 14.73,43.69 16.51,41.91 18.29,41.91 19.12,41.07 19.12,39.96 v1(19.38,39.7) ; v1(19.84,39.7) v1(19.38,39.7) ; v1(19.38,39.7) 19.38,37.63 19.4,37.61 19.4,25.03 21.09,23.34 23.52,23.34 24.91,21.95 24.91,19.77 v1(24.26,19.11)
  LYR4 w0.762: v1(24.05,11.46) 24.05,10.54 23.78,10.27 23.78,8.48 27.3,4.95 P9.8 P9.7
  BOTTOM w0.381: v1(24.26,19.11) 24.26,18.48 C13.2 23.5,18.35 23.5,18.86 23.24,19.11 v1(22.99,19.11) ; v1(19,14.76) 19.15,14.61 C10.2 ; v1(19.84,39.7) 19.81,39.67 C17.1 ; U4.2 19.38,41.22 v1(19.38,39.7) ; C8.2 C7.2 23.81,11.7 v1(24.05,11.46)
  vias: v1(4.34,7.77) v1(4.6,7.39) v1(4.8,7.8) v1(12.78,13.31) v1(13.18,13.54) v1(13.18,13.08)
SYS_RESETN: length 109.5
  TOP w0.121: C24.1 43.17,15.28 D7.2 42.77,16.15 v1(42.42,16.51) 41.91,16.51 41.66,16.76 41.66,18.67 42.93,19.94 43.81,19.94 44.7,20.83 44.7,21.46 45.32,22.08 U5.A10 ; U16.4 31.1,5.7 P9.10 ; S1.2 S1.4 v1(9.83,48.2)
  LYR3 w0.133: v1(42.42,16.51) 41.91,16 38.35,16 38.1,15.75 34.73,15.75 v1(34.29,16.19)
  LYR4 w0.133: v1(9.83,48.2) 9.83,46.35 11.05,45.14 18.41,45.14 22.4,41.15 26.16,41.15 27.05,40.26 28.45,40.26 ; 28.45,40.26 28.45,37.47 30.28,35.64 30.28,19.1 v1(29.97,18.8) 30.48,18.29 30.48,15.75 27.62,12.89 v1(27.62,12.06) 29.31,10.38 29.31,4.98 P9.10 ; 28.45,40.26 28.47,40.26 28.84,40.62 35.42,40.62 v1(35.69,40.89)
  BOTTOM w0.121: v1(29.97,18.8) 30.48,18.29 30.48,16.51 30.8,16.19 P2.15 v1(34.29,16.19) ; v1(27.62,12.06) R14.2 C30.1 ; U6.2 35.81,41.02 v1(35.69,40.89) R148.1 ; D6.2 9.84,47.81 9.83,47.82 v1(9.83,48.2)
TCT_RCT: length 6.4
  BOTTOM w0.121: P5.4 15.88,29.21 P5.5 R137.1 C141.1
TESTOUT: length 2.9
  TOP w0.121: TP3.1 51.44,21.89 U5.A3
TIMER4: length 31.4
  TOP w0.121: v1(48.12,34.01) U5.R7
  LYR3 w0.121: v1(48.12,34.01) 47.72,34.41 47.72,35.05
  LYR3 w0.133: v1(35.18,47.75) 35.97,46.96 40.92,46.96 46.75,41.14 46.75,36.44 47.72,35.46 47.72,35.05
  LYR4 w0.133: v1(35.18,47.75) 34.24,48.69 28.78,48.69 28.34,49.13 28.34,49.13 P8.7
TIMER5: length 28.8
  TOP w0.121: v1(48.92,34.81) U5.T6
  LYR3 w0.133: v1(36.7,47.75) 40.79,47.75 40.98,47.57 40.98,47.57 41.11,47.43 41.11,47.43 47.22,41.33 47.22,41.33 48.36,40.19 48.36,40.19 48.39,40.16 48.39,35.69 48.92,35.15 v1(48.92,34.81)
  LYR4 w0.133: v1(36.7,47.75) 35.29,49.16 30.85,49.16 P8.9
TIMER6: length 37.6
  TOP w0.121: U5.U6 48.92,35.61 48.92,37.24 49.32,37.64 49.32,39.18 49.32,44.49 49.95,45.12 49.95,45.6 49.95,45.6 49.95,46.14 49.95,46.14 49.95,48.37 49.07,49.25 49.07,51.28 v1(49.38,51.59) ; v1(47.96,51.59) 44.35,51.59 v1(44.09,51.84)
  LYR4 w0.133: v1(44.09,51.84) 43.71,51.84 43.51,51.64 30.91,51.64 P8.10 ; v1(49.38,51.59) v1(47.96,51.59)
TIMER7: length 32.9
  TOP w0.121: v1(48.12,34.81) U5.T7
  LYR3 w0.133: v1(48.12,34.81) 48.12,40.09 46.98,41.23 46.98,41.23 41.02,47.2 41.01,47.2 40.88,47.33 36.36,47.33 v1(35.94,47.75)
  LYR4 w0.133: P8.8 28.57,51.44 28.57,49.73 29.38,48.93 34.77,48.93 v1(35.94,47.75)
TXCLK: length 6.1
  TOP w0.121: v1(29.21,35.56) 29.01,35.56 28.85,35.4 28.85,35.39 28.61,35.16 28.61,35.16 28.45,35.01 25.67,35.01 25.33,34.67 U14.20
  BOTTOM w0.121: R134.2 v1(29.21,35.56)
TXD0: length 5.8
  TOP w0.121: R158.2 22.61,38.23 24.33,36.5 U14.22
TXD1: length 4.8
  TOP w0.121: R166.2 22.73,37.34 23.83,36.24 U14.23
TXD2: length 3.8
  TOP w0.121: U14.24 23.33,34.24 23.5,34.4 23.5,35.69 22.73,36.45 R171.2
TXD3: length 4.5
  TOP w0.121: R172.2 22.99,35.56 23.17,35.38 23.17,34.73 22.05,33.61 22.05,33.09 22.28,32.87 U14.25
TXEN: length 6.9
  TOP w0.121: U14.21 24.83,36.89 22.61,39.12 R149.2
TXN: length 20.3
  TOP w0.095: U14.28 21.59,31.37 21.27,31.69 v1(21.27,32.07)
  LYR3 w0.102: v1(21.27,32.07) 20.88,31.68 20.88,31.16 19.81,30.09 19.81,28.45 18.21,26.85 16.71,26.85 15.9,27.66 15.9,29.09 16.15,29.34 16.89,29.34 17.14,29.09 P5.6
  BOTTOM w0.095: R123.1 v1(21.27,32.07)
  BOTTOM w0.121: P5.6 C140.1
TXP: length 17.8
  TOP w0.095: U14.29 22.03,30.86 21.81,31.09 21.28,31.09 21.27,31.1 v1(21.27,31.11)
  LYR3 w0.102: v1(21.27,31.11) 20.12,29.96 20.12,28.32 18.34,26.54 16.59,26.54 15.6,27.53 15.6,30.76 P5.3
  BOTTOM w0.095: R122.1 v1(21.27,31.11)
  BOTTOM w0.121: C139.1 P5.3
U5_H18: length 4.2
  TOP w0.121: U5.H18 38.1,28.01 37.9,27.81 R28.1
U5_R13: length 8.5
  TOP w0.121: v1(42.52,34.01) U5.R13
  LYR3 w0.121: 42.92,35.31 42.92,34.41 v1(42.52,34.01)
  LYR3 w0.133: 42.92,35.31 42.16,36.07 42.16,39.32 v1(42.09,39.4)
  BOTTOM w0.133: v1(42.09,39.4) 42.42,39.73 R160.1
U5_T13: length 7.5
  TOP w0.121: v1(42.52,34.81) U5.T13
  LYR3 w0.133: v1(42.52,34.81) 42.52,35.18 41.9,35.8 41.9,38.9 41.49,39.3 41.49,39.43 v1(41.48,39.45)
  BOTTOM w0.133: v1(41.48,39.45) 41.53,39.5 R161.1
